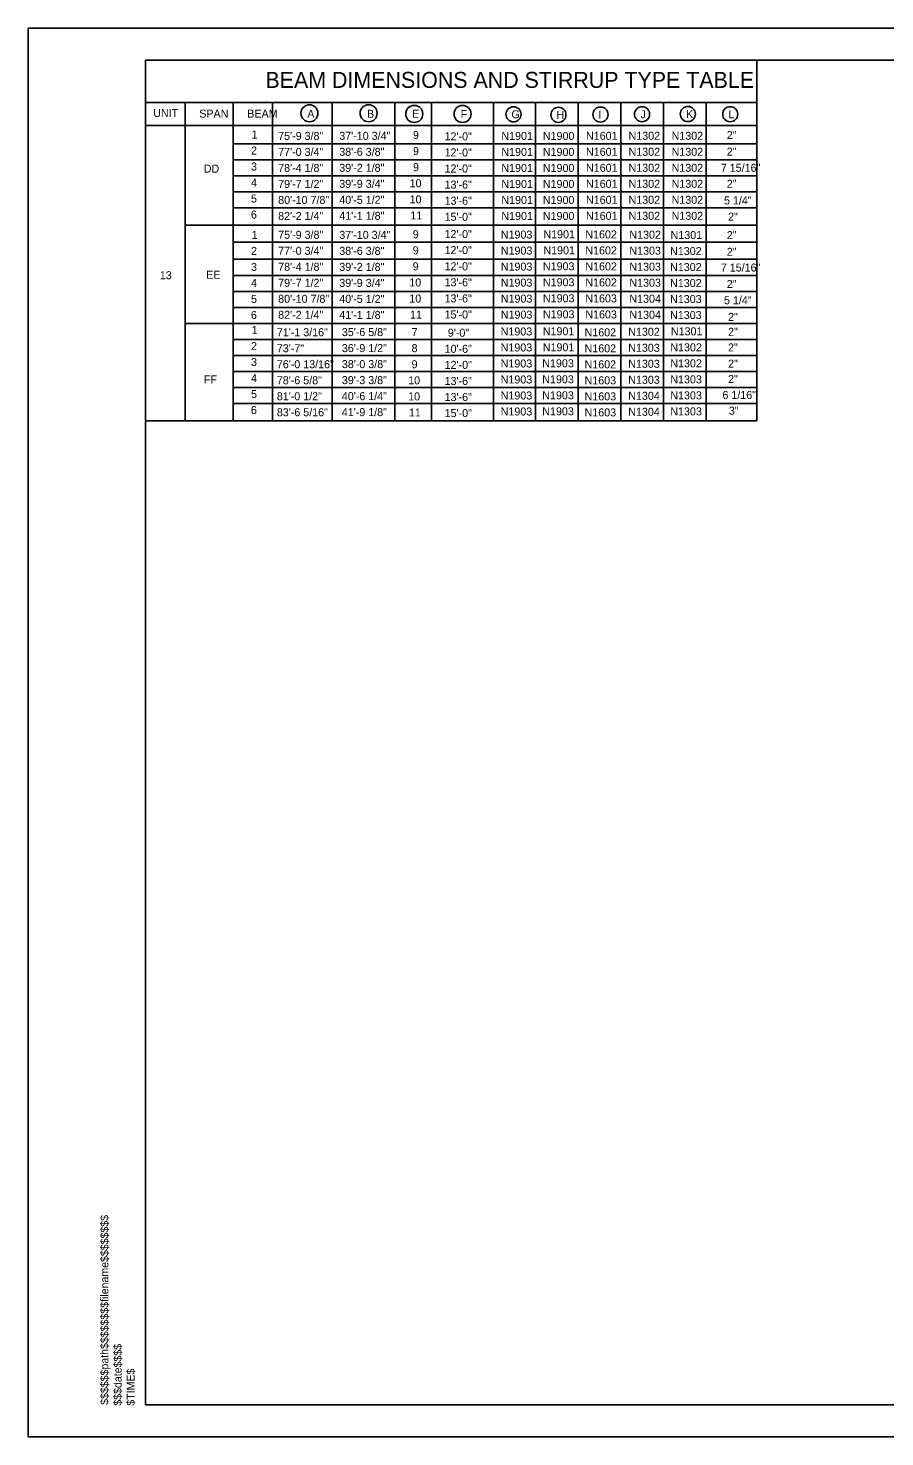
# Model space of a CAD drawing. Extents: x -50.5 to -14.4, y -52.6 to -30.6.
# Drawn here: x -50.52 to -37.13, y -52.58 to -30.58 of the extents above; entities that cross this region are included whole.
import ezdxf

# ---------------------------------------------------------------- set-up
doc = ezdxf.new("R2010")
doc.units = 0
for name, color, linetype in [('BR_AUTO DIMENSION', 7, 'Continuous'), ('BR_BORDER LINES', 7, 'Continuous'), ('BR_TABLE LINES', 7, 'Continuous'), ('BR_TEXT', 7, 'Continuous'), ('Level 31', 7, 'Continuous'), ('RD_SHT_ID', 7, 'Continuous')]:
    doc.layers.add(name, color=color, linetype=linetype)

msp = doc.modelspace()

# ---------------------------------------------------------------- linework, layer by layer
at = {"layer": 'BR_AUTO DIMENSION'}
for centre in [(-46.123, -31.91), (-45.198, -31.91), (-44.485, -31.921), (-43.731, -31.921)]:
    msp.add_circle(centre, 0.133, dxfattribs=at)
at = {"layer": 'BR_BORDER LINES'}
for p, q in [((-48.685, -31.081), (-39.133, -31.081)), ((-48.685, -31.081), (-48.685, -36.712)), ((-15.019, -31.081), (-48.685, -31.081)), ((-48.685, -52.081), (-48.685, -31.081)), ((-39.133, -31.081), (-39.133, -36.712)), ((-48.685, -36.712), (-39.133, -36.712)), ((-48.685, -52.081), (-15.019, -52.081))]:
    msp.add_line(p, q, dxfattribs=at)
at = {"layer": 'BR_TABLE LINES'}
for p, q in [((-48.685, -31.741), (-39.133, -31.744)), ((-48.065, -31.74), (-48.065, -36.712)), ((-47.316, -31.74), (-47.316, -36.712)), ((-46.699, -31.74), (-46.699, -36.712)), ((-45.766, -31.74), (-45.766, -36.712)), ((-44.79, -31.745), (-44.79, -36.712)), ((-44.218, -31.745), (-44.218, -36.712)), ((-43.249, -31.745), (-43.249, -36.712)), ((-42.589, -31.745), (-42.589, -36.712)), ((-41.923, -31.745), (-41.923, -36.712)), ((-41.257, -31.745), (-41.257, -36.712)), ((-40.591, -31.745), (-40.591, -36.712)), ((-39.925, -31.745), (-39.925, -36.712)), ((-48.685, -32.099), (-39.133, -32.099)), ((-47.316, -32.386), (-39.133, -32.386)), ((-47.316, -32.636), (-39.133, -32.636)), ((-47.316, -32.886), (-39.133, -32.886)), ((-47.316, -33.136), (-39.133, -33.136)), ((-47.316, -33.386), (-39.133, -33.386)), ((-48.065, -33.657), (-39.133, -33.657)), ((-47.316, -33.925), (-39.133, -33.925)), ((-47.316, -34.191), (-39.133, -34.191)), ((-47.316, -34.441), (-39.133, -34.441)), ((-47.316, -34.691), (-39.133, -34.691)), ((-47.316, -34.941), (-39.133, -34.941)), ((-48.065, -35.191), (-39.133, -35.191)), ((-47.316, -35.441), (-39.133, -35.441)), ((-47.316, -35.691), (-39.133, -35.691)), ((-47.316, -35.941), (-39.133, -35.941)), ((-47.316, -36.191), (-39.133, -36.191)), ((-47.316, -36.441), (-39.133, -36.441))]:
    msp.add_line(p, q, dxfattribs=at)
at = {"layer": 'BR_TEXT'}
for centre in [(-42.935, -31.926), (-42.233, -31.934), (-41.575, -31.93), (-40.926, -31.925), (-40.21, -31.922), (-39.548, -31.925)]:
    msp.add_circle(centre, 0.118, dxfattribs=at)
at = {"layer": 'Level 31'}
msp.add_lwpolyline([(-50.519, -52.581), (-14.519, -52.581), (-14.519, -30.581), (-50.519, -30.581)], close=True, dxfattribs=at)

# ---------------------------------------------------------------- texts
at = {"layer": 'BR_TEXT'}
for s, height, p in [('BEAM DIMENSIONS AND STIRRUP TYPE TABLE', 0.25, (-46.811, -31.514)), ('E', 0.125, (-44.519, -31.981)), ('F', 0.125, (-43.761, -31.985)), ('1', 0.125, (-47.028, -32.304)), ('75\'-9 3/8"', 0.125, (-46.612, -32.326)), ('37\'-10 3/4"', 0.125, (-45.657, -32.324)), ('9', 0.125, (-44.505, -32.312)), ('12\'-0"', 0.125, (-44.012, -32.333)), ('N1901', 0.125, (-43.124, -32.326)), ('N1900', 0.125, (-42.476, -32.326)), ('N1601', 0.125, (-41.802, -32.324)), ('N1302', 0.125, (-41.137, -32.324)), ('N1302', 0.125, (-40.464, -32.324)), ('2"', 0.125, (-39.602, -32.312)), ('2', 0.125, (-47.036, -32.554)), ('77\'-0 3/4"', 0.125, (-46.612, -32.576)), ('38\'-6 3/8"', 0.125, (-45.657, -32.574)), ('9', 0.125, (-44.505, -32.563)), ('12\'-0"', 0.125, (-44.012, -32.584)), ('N1901', 0.125, (-43.124, -32.576)), ('N1900', 0.125, (-42.476, -32.576)), ('N1601', 0.125, (-41.802, -32.574)), ('N1302', 0.125, (-41.137, -32.574)), ('N1302', 0.125, (-40.464, -32.574)), ('2"', 0.125, (-39.602, -32.571)), ('3', 0.125, (-47.036, -32.804)), ('78\'-4 1/8"', 0.125, (-46.612, -32.826)), ('39\'-2 1/8"', 0.125, (-45.657, -32.824)), ('9', 0.125, (-44.505, -32.814)), ('12\'-0"', 0.125, (-44.012, -32.835)), ('N1901', 0.125, (-43.124, -32.826)), ('N1900', 0.125, (-42.476, -32.826)), ('N1601', 0.125, (-41.802, -32.824)), ('N1302', 0.125, (-41.137, -32.824)), ('N1302', 0.125, (-40.464, -32.824)), ('7 15/16"', 0.125, (-39.695, -32.824)), ('4', 0.125, (-47.036, -33.054)), ('79\'-7 1/2"', 0.125, (-46.612, -33.076)), ('39\'-9 3/4"', 0.125, (-45.657, -33.074)), ('10', 0.125, (-44.558, -33.065)), ('13\'-6"', 0.125, (-44.012, -33.086)), ('N1901', 0.125, (-43.124, -33.076)), ('N1900', 0.125, (-42.476, -33.076)), ('N1601', 0.125, (-41.802, -33.074)), ('N1302', 0.125, (-41.137, -33.074)), ('N1302', 0.125, (-40.464, -33.074)), ('2"', 0.125, (-39.602, -33.074)), ('5', 0.125, (-47.036, -33.304)), ('80\'-10 7/8"', 0.125, (-46.612, -33.326)), ('40\'-5 1/2"', 0.125, (-45.657, -33.324)), ('10', 0.125, (-44.558, -33.317)), ('13\'-6"', 0.125, (-44.012, -33.338)), ('N1901', 0.125, (-43.124, -33.326)), ('N1900', 0.125, (-42.476, -33.326)), ('N1601', 0.125, (-41.802, -33.324)), ('N1302', 0.125, (-41.137, -33.324)), ('N1302', 0.125, (-40.464, -33.324)), ('5 1/4"', 0.125, (-39.645, -33.333)), ('6', 0.125, (-47.038, -33.554)), ('82\'-2 1/4"', 0.125, (-46.612, -33.576)), ('41\'-1 1/8"', 0.125, (-45.657, -33.574)), ('11', 0.125, (-44.546, -33.568)), ('15\'-0"', 0.125, (-44.012, -33.589)), ('N1901', 0.125, (-43.124, -33.576)), ('N1900', 0.125, (-42.476, -33.576)), ('N1601', 0.125, (-41.802, -33.574)), ('N1302', 0.125, (-41.137, -33.574)), ('N1302', 0.125, (-40.464, -33.574)), ('2"', 0.125, (-39.582, -33.587)), ('1', 0.125, (-47.028, -33.872)), ('75\'-9 3/8"', 0.125, (-46.612, -33.87)), ('37\'-10 3/4"', 0.125, (-45.657, -33.871)), ('9', 0.125, (-44.509, -33.862)), ('12\'-0"', 0.125, (-44.012, -33.859)), ('N1903', 0.125, (-43.133, -33.867)), ('N1901', 0.125, (-42.467, -33.862)), ('N1602', 0.125, (-41.812, -33.864)), ('N1302', 0.125, (-41.124, -33.869)), ('N1301', 0.125, (-40.48, -33.874)), ('2"', 0.125, (-39.602, -33.876)), ('2', 0.125, (-47.036, -34.122)), ('77\'-0 3/4"', 0.125, (-46.612, -34.12)), ('38\'-6 3/8"', 0.125, (-45.657, -34.121)), ('9', 0.125, (-44.509, -34.113)), ('12\'-0"', 0.125, (-44.012, -34.11)), ('N1903', 0.125, (-43.133, -34.117)), ('N1901', 0.125, (-42.467, -34.112)), ('N1602', 0.125, (-41.812, -34.114)), ('N1303', 0.125, (-41.124, -34.119)), ('N1302', 0.125, (-40.488, -34.124)), ('2"', 0.125, (-39.602, -34.136)), ('3', 0.125, (-47.036, -34.372)), ('78\'-4 1/8"', 0.125, (-46.612, -34.37)), ('39\'-2 1/8"', 0.125, (-45.657, -34.371)), ('9', 0.125, (-44.509, -34.364)), ('12\'-0"', 0.125, (-44.012, -34.362)), ('N1903', 0.125, (-43.133, -34.367)), ('N1903', 0.125, (-42.475, -34.362)), ('N1602', 0.125, (-41.812, -34.364)), ('N1303', 0.125, (-41.124, -34.369)), ('N1302', 0.125, (-40.488, -34.374)), ('7 15/16"', 0.125, (-39.695, -34.382)), ('4', 0.125, (-47.036, -34.622)), ('79\'-7 1/2"', 0.125, (-46.612, -34.62)), ('39\'-9 3/4"', 0.125, (-45.657, -34.621)), ('10', 0.125, (-44.563, -34.615)), ('13\'-6"', 0.125, (-44.012, -34.613)), ('N1903', 0.125, (-43.133, -34.617)), ('N1903', 0.125, (-42.475, -34.612)), ('N1602', 0.125, (-41.812, -34.614)), ('N1303', 0.125, (-41.124, -34.619)), ('N1302', 0.125, (-40.488, -34.624)), ('2"', 0.125, (-39.602, -34.639)), ('5', 0.125, (-47.036, -34.872)), ('80\'-10 7/8"', 0.125, (-46.612, -34.87)), ('40\'-5 1/2"', 0.125, (-45.657, -34.871)), ('10', 0.125, (-44.563, -34.866)), ('13\'-6"', 0.125, (-44.012, -34.864)), ('N1903', 0.125, (-43.133, -34.867)), ('N1903', 0.125, (-42.475, -34.862)), ('N1603', 0.125, (-41.812, -34.864)), ('N1304', 0.125, (-41.124, -34.869)), ('N1303', 0.125, (-40.488, -34.874)), ('5 1/4"', 0.125, (-39.645, -34.892)), ('6', 0.125, (-47.038, -35.122)), ('82\'-2 1/4"', 0.125, (-46.612, -35.12)), ('41\'-1 1/8"', 0.125, (-45.657, -35.121)), ('11', 0.125, (-44.551, -35.117)), ('15\'-0"', 0.125, (-44.012, -35.115)), ('N1903', 0.125, (-43.133, -35.117)), ('N1903', 0.125, (-42.475, -35.112)), ('N1603', 0.125, (-41.812, -35.114)), ('N1304', 0.125, (-41.124, -35.119)), ('N1303', 0.125, (-40.488, -35.124)), ('2"', 0.125, (-39.582, -35.152)), ('1', 0.125, (-47.028, -35.358)), ('71\'-1 3/16"', 0.125, (-46.633, -35.392)), ('35\'-6 5/8"', 0.125, (-45.617, -35.39)), ('7', 0.125, (-44.527, -35.39)), ('9\'-0"', 0.125, (-43.961, -35.4)), ('N1903', 0.125, (-43.135, -35.38)), ('N1901', 0.125, (-42.477, -35.377)), ('N1602', 0.125, (-41.824, -35.394)), ('N1302', 0.125, (-41.142, -35.385)), ('N1301', 0.125, (-40.475, -35.378)), ('2"', 0.125, (-39.582, -35.385)), ('2', 0.125, (-47.036, -35.608)), ('73\'-7"', 0.125, (-46.633, -35.642)), ('36\'-9 1/2"', 0.125, (-45.617, -35.64)), ('8', 0.125, (-44.527, -35.641)), ('10\'-6"', 0.125, (-44.011, -35.651)), ('N1903', 0.125, (-43.135, -35.63)), ('N1901', 0.125, (-42.477, -35.627)), ('N1602', 0.125, (-41.824, -35.644)), ('N1303', 0.125, (-41.142, -35.635)), ('N1302', 0.125, (-40.484, -35.628)), ('2"', 0.125, (-39.582, -35.629)), ('3', 0.125, (-47.036, -35.858)), ('76\'-0 13/16"', 0.125, (-46.633, -35.892)), ('38\'-0 3/8"', 0.125, (-45.617, -35.89)), ('9', 0.125, (-44.527, -35.892)), ('12\'-0"', 0.125, (-44.011, -35.902)), ('N1903', 0.125, (-43.135, -35.88)), ('N1903', 0.125, (-42.485, -35.877)), ('N1602', 0.125, (-41.824, -35.894)), ('N1303', 0.125, (-41.142, -35.885)), ('N1302', 0.125, (-40.484, -35.878)), ('2"', 0.125, (-39.582, -35.883)), ('4', 0.125, (-47.036, -36.108)), ('78\'-6 5/8"', 0.125, (-46.633, -36.142)), ('39\'-3 3/8"', 0.125, (-45.617, -36.14)), ('10', 0.125, (-44.581, -36.143)), ('13\'-6"', 0.125, (-44.011, -36.153)), ('N1903', 0.125, (-43.135, -36.13)), ('N1903', 0.125, (-42.485, -36.127)), ('N1603', 0.125, (-41.824, -36.144)), ('N1303', 0.125, (-41.142, -36.135)), ('N1303', 0.125, (-40.484, -36.128)), ('2"', 0.125, (-39.582, -36.123)), ('5', 0.125, (-47.036, -36.358)), ('81\'-0 1/2"', 0.125, (-46.633, -36.392)), ('40\'-6 1/4"', 0.125, (-45.617, -36.39)), ('10', 0.125, (-44.581, -36.394)), ('13\'-6"', 0.125, (-44.011, -36.404)), ('N1903', 0.125, (-43.135, -36.38)), ('N1903', 0.125, (-42.485, -36.377)), ('N1603', 0.125, (-41.824, -36.394)), ('N1304', 0.125, (-41.142, -36.385)), ('N1303', 0.125, (-40.484, -36.378)), ('6 1/16"', 0.125, (-39.67, -36.372)), ('6', 0.125, (-47.038, -36.608)), ('83\'-6 5/16"', 0.125, (-46.633, -36.642)), ('41\'-9 1/8"', 0.125, (-45.617, -36.64)), ('N1903', 0.125, (-43.135, -36.63)), ('N1903', 0.125, (-42.485, -36.627)), ('N1603', 0.125, (-41.824, -36.644)), ('N1304', 0.125, (-41.142, -36.635)), ('N1303', 0.125, (-40.484, -36.628)), ('3"', 0.125, (-39.57, -36.618)), ('11', 0.125, (-44.569, -36.645)), ('15\'-0"', 0.125, (-44.011, -36.655))]:
    msp.add_text(s, height=height, dxfattribs=at).set_placement(p)
for s, p in [('UNIT', (-48.564, -31.968)), ('SPAN', (-47.845, -31.978)), ('BEAM', (-47.095, -31.978)), ('A', (-46.157, -31.981)), ('B', (-45.224, -31.981)), ('G', (-42.967, -31.988)), ('H', (-42.262, -31.997)), ('I', (-41.608, -31.993)), ('J', (-40.95, -31.987)), ('K', (-40.239, -31.985)), ('L', (-39.577, -31.988)), ('DD', (-47.774, -32.837)), ('13', (-48.461, -34.502)), ('EE', (-47.737, -34.494)), ('FF', (-47.772, -36.13))]:
    msp.add_text(s, height=0.125, rotation=360, dxfattribs=at).set_placement(p)
at = {"layer": 'RD_SHT_ID'}
for s, height, p in [('$$$$$$path$$$$$$$$filename$$$$$$$$', 0.12347, (-49.265, -52.081)), ('$$$date$$$$', 0.12347, (-49.059, -52.094)), ('$TIME$', 0.1235, (-48.855, -52.094))]:
    msp.add_text(s, height=height, rotation=90, dxfattribs=at).set_placement(p)

doc.saveas('drawing.dxf')
